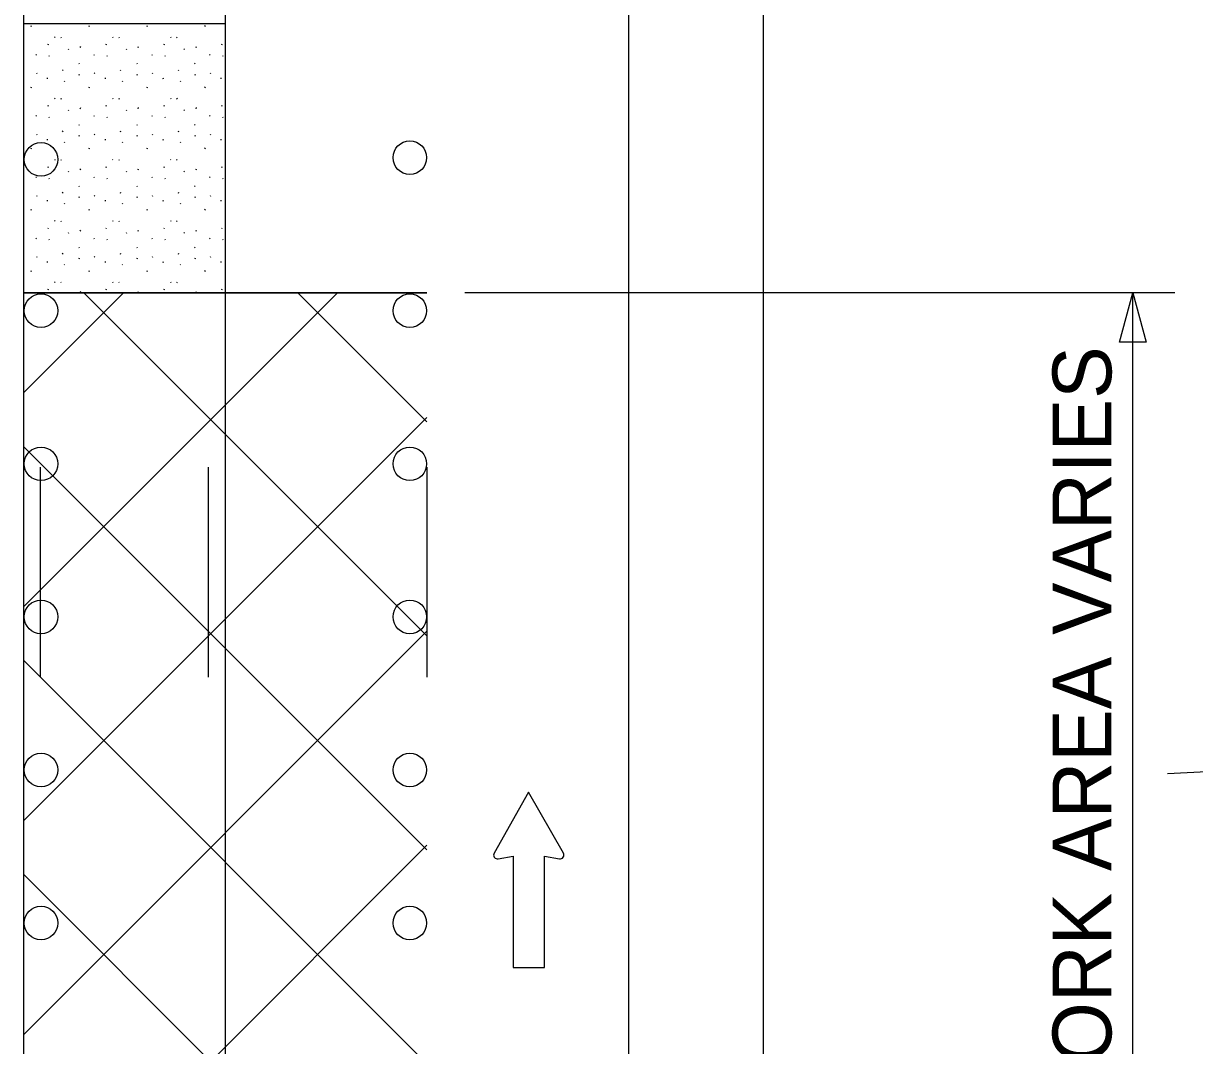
# Model space of a CAD drawing. Extents: x 16733 to 18475, y 5693 to 6915.
# Drawn here: x 17011.4 to 17150.8, y 6506.8 to 6628.4 of the extents above; entities that cross this region are included whole.
import ezdxf

# ---------------------------------------------------------------- set-up
doc = ezdxf.new("R2010")
doc.units = 0
for name, color, linetype in [('ALI_LEGAL_EX', 7, 'Continuous'), ('MT_SCRATCH_LEVEL_A', 7, 'Continuous'), ('MT_SCRATCH_LEVEL_E', 7, 'Continuous'), ('PAVT_EDGE_EX', 7, 'Continuous'), ('TRAFFIC_SIGNS_PR', 7, 'Continuous'), ('TYPICAL_TEXT_DIMEN_PR', 7, 'Continuous')]:
    doc.layers.add(name, color=color, linetype=linetype)

msp = doc.modelspace()

# ---------------------------------------------------------------- linework, layer by layer
at = {"layer": 'ALI_LEGAL_EX'}
for points in [[(17013.43, 6575.6), (17013.43, 6550.6)], [(17033.43, 6575.6), (17033.43, 6550.6)], [(17059.43, 6575.6), (17059.43, 6550.6)]]:
    msp.add_lwpolyline(points, dxfattribs=at)
at = {"layer": 'MT_SCRATCH_LEVEL_A'}
for p, q in [((17011.43, 6628.39), (17035.43, 6628.39)), ((17011.43, 6628.39), (17011.43, 6450.54)), ((17011.43, 6628.39), (17011.43, 6596.33)), ((17012.36, 6628.03), (17012.41, 6628.15)), ((17019.25, 6628.03), (17019.3, 6628.15)), ((17026.14, 6628.03), (17026.19, 6628.15)), ((17033.02, 6628.03), (17033.08, 6628.15)), ((17014.38, 6625.83), (17014.43, 6625.95)), ((17015.15, 6626.79), (17015.2, 6626.71)), ((17015.88, 6626.76), (17015.93, 6626.69)), ((17021.27, 6625.83), (17021.32, 6625.95)), ((17022.03, 6626.79), (17022.08, 6626.71)), ((17022.77, 6626.76), (17022.82, 6626.69)), ((17028.16, 6625.83), (17028.21, 6625.95)), ((17028.92, 6626.79), (17028.97, 6626.71)), ((17029.66, 6626.76), (17029.71, 6626.69)), ((17035.04, 6625.83), (17035.1, 6625.95)), ((17012.93, 6624.71), (17012.98, 6624.63)), ((17014.46, 6624.57), (17014.51, 6624.49)), ((17016.75, 6625.38), (17016.8, 6625.31)), ((17018.2, 6625.53), (17018.25, 6625.65)), ((17019.82, 6624.71), (17019.87, 6624.63)), ((17021.35, 6624.57), (17021.4, 6624.49)), ((17023.64, 6625.38), (17023.69, 6625.31)), ((17025.09, 6625.53), (17025.14, 6625.65)), ((17026.71, 6624.71), (17026.76, 6624.63)), ((17028.24, 6624.57), (17028.29, 6624.49)), ((17030.53, 6625.38), (17030.58, 6625.31)), ((17031.97, 6625.53), (17032.03, 6625.65)), ((17033.59, 6624.71), (17033.65, 6624.63)), ((17035.12, 6624.57), (17035.17, 6624.49)), ((17018.03, 6623.65), (17018.08, 6623.57)), ((17024.92, 6623.65), (17024.97, 6623.57)), ((17031.8, 6623.65), (17031.85, 6623.57)), ((17012.98, 6622.5), (17013.03, 6622.42)), ((17014.26, 6621.92), (17014.27, 6621.8)), ((17016.1, 6622.78), (17016.15, 6622.89)), ((17016.29, 6621.58), (17016.34, 6621.5)), ((17018.07, 6622.25), (17018.12, 6622.36)), ((17019.87, 6622.5), (17019.92, 6622.42)), ((17021.15, 6621.92), (17021.16, 6621.8)), ((17022.99, 6622.78), (17023.04, 6622.89)), ((17023.18, 6621.58), (17023.23, 6621.5)), ((17024.96, 6622.25), (17025.01, 6622.36)), ((17026.76, 6622.5), (17026.81, 6622.42)), ((17028.04, 6621.92), (17028.05, 6621.8)), ((17029.88, 6622.78), (17029.93, 6622.89)), ((17030.07, 6621.58), (17030.12, 6621.5)), ((17031.85, 6622.25), (17031.9, 6622.36)), ((17033.64, 6622.5), (17033.69, 6622.42)), ((17034.92, 6621.92), (17034.94, 6621.8)), ((17012.36, 6620.74), (17012.41, 6620.86)), ((17019.25, 6620.74), (17019.3, 6620.86)), ((17026.14, 6620.74), (17026.19, 6620.86)), ((17033.02, 6620.74), (17033.08, 6620.86)), ((17015.15, 6619.51), (17015.2, 6619.43)), ((17015.88, 6619.48), (17015.93, 6619.4)), ((17022.03, 6619.51), (17022.08, 6619.43)), ((17022.77, 6619.48), (17022.82, 6619.4)), ((17028.92, 6619.51), (17028.97, 6619.43)), ((17029.66, 6619.48), (17029.71, 6619.4)), ((17012.93, 6617.42), (17012.98, 6617.34)), ((17014.38, 6618.55), (17014.43, 6618.66)), ((17016.75, 6618.1), (17016.8, 6618.02)), ((17018.2, 6618.25), (17018.25, 6618.37)), ((17019.82, 6617.42), (17019.87, 6617.34)), ((17021.27, 6618.55), (17021.32, 6618.66)), ((17023.64, 6618.1), (17023.69, 6618.02)), ((17025.09, 6618.25), (17025.14, 6618.37)), ((17026.71, 6617.42), (17026.76, 6617.34)), ((17028.16, 6618.55), (17028.21, 6618.66)), ((17030.53, 6618.1), (17030.58, 6618.02)), ((17031.97, 6618.25), (17032.03, 6618.37)), ((17033.59, 6617.42), (17033.65, 6617.34)), ((17035.04, 6618.55), (17035.1, 6618.66)), ((17014.46, 6617.28), (17014.51, 6617.2)), ((17018.03, 6616.36), (17018.08, 6616.28)), ((17021.35, 6617.28), (17021.4, 6617.2)), ((17024.92, 6616.36), (17024.97, 6616.28)), ((17028.24, 6617.28), (17028.29, 6617.2)), ((17031.8, 6616.36), (17031.85, 6616.28)), ((17035.12, 6617.28), (17035.17, 6617.2)), ((17012.98, 6615.21), (17013.03, 6615.13)), ((17014.26, 6614.64), (17014.27, 6614.52)), ((17016.1, 6615.49), (17016.15, 6615.61)), ((17018.07, 6614.96), (17018.12, 6615.08)), ((17019.87, 6615.21), (17019.92, 6615.13)), ((17021.15, 6614.64), (17021.16, 6614.52)), ((17022.99, 6615.49), (17023.04, 6615.61)), ((17024.96, 6614.96), (17025.01, 6615.08)), ((17026.76, 6615.21), (17026.81, 6615.13)), ((17028.04, 6614.64), (17028.05, 6614.52)), ((17029.88, 6615.49), (17029.93, 6615.61)), ((17031.85, 6614.96), (17031.9, 6615.08)), ((17033.64, 6615.21), (17033.69, 6615.13)), ((17034.92, 6614.64), (17034.94, 6614.52)), ((17012.36, 6613.46), (17012.41, 6613.58)), ((17016.29, 6614.29), (17016.34, 6614.22)), ((17019.25, 6613.46), (17019.3, 6613.58)), ((17023.18, 6614.29), (17023.23, 6614.22)), ((17026.14, 6613.46), (17026.19, 6613.58)), ((17030.07, 6614.29), (17030.12, 6614.22)), ((17033.02, 6613.46), (17033.08, 6613.58)), ((17015.15, 6612.22), (17015.2, 6612.15)), ((17015.88, 6612.19), (17015.93, 6612.11)), ((17022.03, 6612.22), (17022.08, 6612.15)), ((17022.77, 6612.19), (17022.82, 6612.11)), ((17028.92, 6612.22), (17028.97, 6612.15)), ((17029.66, 6612.19), (17029.71, 6612.11)), ((17014.38, 6611.26), (17014.43, 6611.38)), ((17016.75, 6610.81), (17016.8, 6610.74)), ((17018.2, 6610.97), (17018.25, 6611.08)), ((17021.27, 6611.26), (17021.32, 6611.38)), ((17023.64, 6610.81), (17023.69, 6610.74)), ((17025.09, 6610.97), (17025.14, 6611.08)), ((17028.16, 6611.26), (17028.21, 6611.38)), ((17030.53, 6610.81), (17030.58, 6610.74)), ((17031.97, 6610.97), (17032.03, 6611.08)), ((17035.04, 6611.26), (17035.1, 6611.38)), ((17012.93, 6610.14), (17012.98, 6610.06)), ((17014.46, 6610), (17014.51, 6609.92)), ((17018.03, 6609.08), (17018.08, 6609)), ((17019.82, 6610.14), (17019.87, 6610.06)), ((17021.35, 6610), (17021.4, 6609.92)), ((17024.92, 6609.08), (17024.97, 6609)), ((17026.71, 6610.14), (17026.76, 6610.06)), ((17028.24, 6610), (17028.29, 6609.92)), ((17031.8, 6609.08), (17031.85, 6609)), ((17033.59, 6610.14), (17033.65, 6610.06)), ((17035.12, 6610), (17035.17, 6609.92)), ((17012.98, 6607.93), (17013.03, 6607.85)), ((17016.1, 6608.21), (17016.15, 6608.32)), ((17018.07, 6607.68), (17018.12, 6607.79)), ((17019.87, 6607.93), (17019.92, 6607.85)), ((17022.99, 6608.21), (17023.04, 6608.32)), ((17024.96, 6607.68), (17025.01, 6607.79)), ((17026.76, 6607.93), (17026.81, 6607.85)), ((17029.88, 6608.21), (17029.93, 6608.32)), ((17031.85, 6607.68), (17031.9, 6607.79)), ((17033.64, 6607.93), (17033.69, 6607.85)), ((17012.36, 6606.17), (17012.41, 6606.29)), ((17014.26, 6607.35), (17014.27, 6607.24)), ((17016.29, 6607.01), (17016.34, 6606.93)), ((17019.25, 6606.17), (17019.3, 6606.29)), ((17021.15, 6607.35), (17021.16, 6607.24)), ((17023.18, 6607.01), (17023.23, 6606.93)), ((17026.14, 6606.17), (17026.19, 6606.29)), ((17028.04, 6607.35), (17028.05, 6607.24)), ((17030.07, 6607.01), (17030.12, 6606.93)), ((17033.02, 6606.17), (17033.08, 6606.29)), ((17034.92, 6607.35), (17034.94, 6607.24)), ((17015.15, 6604.94), (17015.2, 6604.86)), ((17015.88, 6604.91), (17015.93, 6604.83)), ((17022.03, 6604.94), (17022.08, 6604.86)), ((17022.77, 6604.91), (17022.82, 6604.83)), ((17028.92, 6604.94), (17028.97, 6604.86)), ((17029.66, 6604.91), (17029.71, 6604.83)), ((17014.38, 6603.98), (17014.43, 6604.09)), ((17016.75, 6603.53), (17016.8, 6603.45)), ((17018.2, 6603.68), (17018.25, 6603.8)), ((17021.27, 6603.98), (17021.32, 6604.09)), ((17023.64, 6603.53), (17023.69, 6603.45)), ((17025.09, 6603.68), (17025.14, 6603.8)), ((17028.16, 6603.98), (17028.21, 6604.09)), ((17030.53, 6603.53), (17030.58, 6603.45)), ((17031.97, 6603.68), (17032.03, 6603.8)), ((17035.04, 6603.98), (17035.1, 6604.09)), ((17012.93, 6602.85), (17012.98, 6602.77)), ((17014.46, 6602.71), (17014.51, 6602.63)), ((17019.82, 6602.85), (17019.87, 6602.77)), ((17021.35, 6602.71), (17021.4, 6602.63)), ((17026.71, 6602.85), (17026.76, 6602.77)), ((17028.24, 6602.71), (17028.29, 6602.63)), ((17033.59, 6602.85), (17033.65, 6602.77)), ((17035.12, 6602.71), (17035.17, 6602.63)), ((17016.1, 6600.92), (17016.15, 6601.04)), ((17018.03, 6601.79), (17018.08, 6601.71)), ((17022.99, 6600.92), (17023.04, 6601.04)), ((17024.92, 6601.79), (17024.97, 6601.71)), ((17029.88, 6600.92), (17029.93, 6601.04)), ((17031.8, 6601.79), (17031.85, 6601.71)), ((17012.98, 6600.64), (17013.03, 6600.57)), ((17014.26, 6600.07), (17014.27, 6599.95)), ((17016.29, 6599.72), (17016.34, 6599.65)), ((17018.07, 6600.39), (17018.12, 6600.51)), ((17019.87, 6600.64), (17019.92, 6600.57)), ((17021.15, 6600.07), (17021.16, 6599.95)), ((17023.18, 6599.72), (17023.23, 6599.65)), ((17024.96, 6600.39), (17025.01, 6600.51)), ((17026.76, 6600.64), (17026.81, 6600.57)), ((17028.04, 6600.07), (17028.05, 6599.95)), ((17030.07, 6599.72), (17030.12, 6599.65)), ((17031.85, 6600.39), (17031.9, 6600.51)), ((17033.64, 6600.64), (17033.69, 6600.57)), ((17034.92, 6600.07), (17034.94, 6599.95)), ((17012.36, 6598.89), (17012.41, 6599.01)), ((17019.25, 6598.89), (17019.3, 6599.01)), ((17026.14, 6598.89), (17026.19, 6599.01)), ((17033.02, 6598.89), (17033.08, 6599.01)), ((17014.38, 6596.69), (17014.43, 6596.81)), ((17015.15, 6597.65), (17015.2, 6597.57)), ((17015.88, 6597.62), (17015.93, 6597.55)), ((17018.2, 6596.4), (17018.25, 6596.51)), ((17021.27, 6596.69), (17021.32, 6596.81)), ((17022.03, 6597.65), (17022.08, 6597.57)), ((17022.77, 6597.62), (17022.82, 6597.55)), ((17025.09, 6596.4), (17025.14, 6596.51)), ((17028.16, 6596.69), (17028.21, 6596.81)), ((17028.92, 6597.65), (17028.97, 6597.57)), ((17029.66, 6597.62), (17029.71, 6597.55)), ((17031.97, 6596.4), (17032.03, 6596.51)), ((17035.04, 6596.69), (17035.1, 6596.81)), ((17011.43, 6596.33), (17059.43, 6596.33)), ((17059.43, 6596.33), (17011.43, 6596.33)), ((17011.43, 6596.33), (17011.43, 6482.6)), ((17011.43, 6596.33), (17059.43, 6596.33)), ((17011.43, 6584.43), (17023.34, 6596.33)), ((17011.43, 6558.97), (17048.79, 6596.33)), ((17059.43, 6555.52), (17018.62, 6596.33)), ((17059.43, 6580.97), (17044.08, 6596.33)), ((17011.43, 6533.52), (17059.43, 6581.52)), ((17059.43, 6530.06), (17011.43, 6578.06)), ((17011.43, 6508.06), (17059.43, 6556.06)), ((17059.43, 6504.61), (17011.43, 6552.61)), ((17011.43, 6482.6), (17059.43, 6530.6)), ((17055.98, 6482.6), (17011.43, 6527.15))]:
    msp.add_line(p, q, dxfattribs=at)
at = {"layer": 'MT_SCRATCH_LEVEL_E'}
for p, q in [((17071.54, 6536.91), (17067.43, 6529.67)), ((17071.54, 6536.91), (17067.43, 6529.67)), ((17075.69, 6529.67), (17071.54, 6536.91)), ((17075.69, 6529.67), (17071.54, 6536.91)), ((17067.91, 6528.99), (17069.69, 6529.3)), ((17067.91, 6528.99), (17069.69, 6529.3)), ((17069.69, 6529.3), (17069.69, 6516.04)), ((17069.69, 6529.3), (17069.69, 6516.04)), ((17073.43, 6516.04), (17073.43, 6529.3)), ((17073.43, 6529.3), (17075.21, 6528.99)), ((17073.43, 6516.04), (17073.43, 6529.3)), ((17073.43, 6529.3), (17075.21, 6528.99)), ((17069.69, 6516.04), (17073.43, 6516.04)), ((17069.69, 6516.04), (17073.43, 6516.04))]:
    msp.add_line(p, q, dxfattribs=at)
for centre, start, end in [((17067.84, 6529.45), 150.4248, 279.9638), ((17067.84, 6529.45), 150.4248, 279.9638), ((17075.28, 6529.45), 260.0362, 29.7731), ((17075.28, 6529.45), 260.0362, 29.7731)]:
    msp.add_arc(centre, 0.463, start, end, dxfattribs=at)
at = {"layer": 'PAVT_EDGE_EX'}
for p, q in [((17011.43, 6893.09), (17011.43, 6095.81)), ((17035.43, 6893.09), (17035.43, 6095.81)), ((17083.43, 6893.09), (17083.43, 6095.81)), ((17099.43, 6893.09), (17099.43, 6095.81))]:
    msp.add_line(p, q, dxfattribs=at)
at = {"layer": 'TRAFFIC_SIGNS_PR'}
for centre in [(17013.53, 6612.21), (17057.41, 6612.42), (17013.53, 6594.21), (17057.41, 6594.21), (17013.53, 6575.99), (17057.41, 6575.99), (17013.53, 6557.78), (17057.41, 6557.78), (17013.53, 6539.56), (17057.41, 6539.56), (17013.53, 6521.35), (17057.41, 6521.35)]:
    msp.add_circle(centre, 2, dxfattribs=at)
msp.add_open_spline([(17195.74, 6526.05), (17138.1, 6523.72), (17223.12, 6543.07), (17147.56, 6539.12)], degree=2, dxfattribs=at)
at = {"layer": 'TYPICAL_TEXT_DIMEN_PR'}
for p, q in [((17148.43, 6596.33), (17063.94, 6596.33)), ((17141.86, 6590.47), (17143.43, 6596.33)), ((17143.43, 6482.6), (17143.43, 6596.33)), ((17143.43, 6596.33), (17145, 6590.47)), ((17143.43, 6590.47), (17141.86, 6590.47)), ((17145, 6590.47), (17143.43, 6590.47))]:
    msp.add_line(p, q, dxfattribs=at)

# ---------------------------------------------------------------- texts
msp.add_text('WORK AREA VARIES', height=7, rotation=90, dxfattribs=at).set_placement((17140.88, 6495.82))

doc.saveas('drawing.dxf')
